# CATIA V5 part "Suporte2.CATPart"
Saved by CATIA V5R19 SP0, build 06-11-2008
Part number: Suporte2
Bounding box of the stored display mesh (mm): x 0 to 3, y -70.792 to 62.208, z -51 to 39
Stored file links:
  C:\Documents and Settings\Proprietário\Ambiente de trabalho\Coluna\Suporte2\Suporte2.CATPart
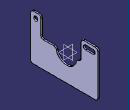
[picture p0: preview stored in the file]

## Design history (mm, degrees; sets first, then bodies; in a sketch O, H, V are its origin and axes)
Body1 (main body)
  Sketch1 on yz-plane, origin (0, 0, 0), H (0, 1, 0), V (0, 0, 1)
    line L1 (1.2838, -51) -> (-70.7917, -51)
    line L2 (-70.7917, -51) -> (-70.7917, 39)
    line L3 (-70.7917, 39) -> (-50.7917, 39)
    line L4 (-50.7917, 39) -> (-50.7917, 0)
    point P5 (-50.7917, 0)
    line L5 (-50.7917, 0) -> (-20.5, 0)
    point P6 (-20.5, 0)
    circle A1 centre (-60.7917, 28.7565) radius 4.25
    point P7 (-60.7917, 28.7565)
    arc A2 centre (0, 0) radius 20.5 from (-20.5, 0) to (20.5, 0) ccw
    line L6 (1.2838, -51) -> (62.2083, -51)
    line L7 (62.2083, -51) -> (62.2083, 38.7565)
    line L8 (20.5, 0) -> (29.2083, 0)
    point P10 (20.5, 0)
    line L9 (29.2083, 0) -> (29.2083, 38.7565)
    line L10 (29.2083, 38.7565) -> (62.2083, 38.7565)
    point P13 (41.2083, 28.7565)
    point P14 (-20.5, 0)
    point P15 (20.5, 0)
    construction line L11 (-60.7917, 28.7565) -> (36.1296, 28.7565)
    construction line L12 (37.8892, 28.7565) -> (52.8892, 28.7565)
    point P17 (37.8892, 28.7565)
    line L13 (37.8892, 33.0065) -> (52.8892, 33.0065)
    line L14 (52.8892, 24.5065) -> (37.8892, 24.5065)
    arc A3 centre (52.8892, 28.7565) radius 4.25 from (52.8892, 33.0065) to (52.8892, 24.5065) cw
    arc A4 centre (37.8892, 28.7565) radius 4.25 from (37.8892, 24.5065) to (37.8892, 33.0065) cw
    distance P7 O = 67.25
    distance O P13 = 50.25
    radius A2 = 20.5
    radius A1 = 4.25
    distance L9 P13 = 12
    distance P7 L4 = 10
    length L3 = 20
    distance P7 P13 = 102
    radius A3 = 4.25
    length L10 = 33
    length L2 = 90
    length L14 = 15
    distance L3 L5 = 39
    horizontal: L1 H, L3 H, L5 H, L6 H, L8 H, L10 H, L11 H, L12 H
    vertical: L2 V, L4 V, L7 V, L9 V
    coincidence: P5 H, A2 P6, P10 A2, P10 H, L8 P15, L5 P14, L11 P13, P17 L11, P6 P14, P10 P15
    tangency: A3 L13, A4 L13, A3 L14, A4 L14
  Pad1: profile Sketch1, direction (1, 0, 0), length 3
  Fillet1: radius 5, on edge [face of Pad1 from Sketch1.L10 | face of Pad1 from Sketch1.L7]
  Fillet2: radius 5, on edge [face of Pad1 from Sketch1.L9 | face of Pad1 from Sketch1.L10]
  Fillet3: radius 5, on edge [face of Pad1 from Sketch1.L8 | face of Pad1 from Sketch1.L9]
  Fillet4: radius 5, on edge [face of Pad1 from Sketch1.A2 | face of Pad1 from Sketch1.L8]
  Fillet5: radius 5, on edge [face of Pad1 from Sketch1.L5 | face of Pad1 from Sketch1.A2]
  Fillet6: radius 5, on edge [face of Pad1 from Sketch1.L4 | face of Pad1 from Sketch1.L5]
  Fillet7: radius 5, on edge [face of Pad1 from Sketch1.L3 | face of Pad1 from Sketch1.L4]
  Fillet8: radius 5, on edge [face of Pad1 from Sketch1.L2 | face of Pad1 from Sketch1.L3]
  Fillet9: radius 5, on edge [face of Pad1 from Sketch1.L1 | face of Pad1 from Sketch1.L2]
  Fillet10: radius 5, on edge [face of Pad1 from Sketch1.L7 | face of Pad1 from Sketch1.L6]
